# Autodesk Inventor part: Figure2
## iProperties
Shininess: 77.0
Length Units: 11269
Angle Units: 11279
Time Units: 11290
Mass Units: 11283
Length Display Precision: 3
Angle Display Precision: 2
Created: 2001-12
Part Number: Figure2
Document SubType Name: Modeling
Designer: CADSoft
Density: 0.0
Volumn: 0.0
Area: 0.0
PropertySet Name: Model Information
Control State: 0
Master: False
Checked Out: False
Author: CADSoft
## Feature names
1. Sweep6
